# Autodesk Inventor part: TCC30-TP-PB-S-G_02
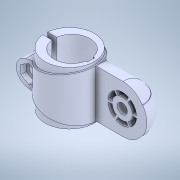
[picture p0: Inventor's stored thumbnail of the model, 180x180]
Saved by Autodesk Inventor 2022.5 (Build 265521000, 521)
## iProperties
Created: 2023-09
Part Number: TCC30-TP-PB-S-G_02
Material: 一般
Document SubType Name: Modeling
Designer: ImaoCorp
Density: 1 g/cm^3
Appearance: 既定
Author: ImaoCorp
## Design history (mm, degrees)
feature "TCC30-TP-PB-S-G_02"
node "ソリッド1"
